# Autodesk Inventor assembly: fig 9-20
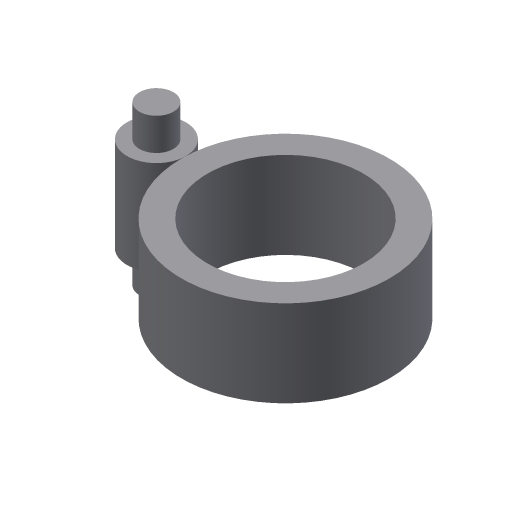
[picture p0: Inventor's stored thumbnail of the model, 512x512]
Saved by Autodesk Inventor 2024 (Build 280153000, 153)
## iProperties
Shininess: 64.0
Length Units: 11269
Angle Units: 11279
Time Units: 11290
Mass Units: 11283
Length Display Precision: 3
Angle Display Precision: 2
Created: 2002-01
Part Number: fig 9-20
Document SubType Name: Assembly
Designer: ***
Density: 0.0
Volumn: 0.0
Area: 0.0
PropertySet Name: Model Information
Control State: 0
Master: False
Checked Out: False
Author: ***
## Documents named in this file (3)
- D:\PROJECTS\Project 2023\RESOURCES INVENTOR 2024\RESOURCES INVENTOR 2024\Inventor_2023_Part\Inventor_2024_Part\c09_Inv_2024_prt\fig 9-20.iam
- D:\PROJECTS\Project 2023\RESOURCES INVENTOR 2024\RESOURCES INVENTOR 2024\Inventor_2023_Part\Inventor_2024_Part\c09_Inv_2024_prt\Part8.ipt
- D:\PROJECTS\Project 2023\RESOURCES INVENTOR 2024\RESOURCES INVENTOR 2024\Inventor_2023_Part\Inventor_2024_Part\c09_Inv_2024_prt\Part9.ipt
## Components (2 placed, 2 different names)
1. Part8:1 — Flush:1
2. Part9:1 — Flush:1
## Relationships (1: Flush 1)
- Flush:1: Part8:1 ↔ Part9:1
